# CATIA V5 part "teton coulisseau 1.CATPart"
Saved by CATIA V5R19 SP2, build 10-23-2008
Part number: teton coulisseau 1
Bounding box of the stored display mesh (mm): x -65 to -55, y -11 to -9, z -1 to 1
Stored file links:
  C:\Users\Thinkmotion2\Desktop\Pack 1\IAO_2010_1396_fvigouroux\vigouroux\vigouroux\teton coulisseau 1.CATPart
  C:\Users\Thinkmotion2\Desktop\Pack 1\IAO_2010_1396_fvigouroux\vigouroux\vigouroux\mecanisme IAO.CATProduct
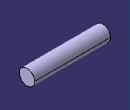
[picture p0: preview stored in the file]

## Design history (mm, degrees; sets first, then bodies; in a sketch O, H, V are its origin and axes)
Set1
  Plane1 to Plane3: linked copy from another document
  Point1: linked copy from another document
Body1 (main body)
  Sketch1 on Plane1, origin (-55, 0, 0), H (0, 1, 0), V (0, 0, 1)
    circle A1 centre (-10, 0) radius 1
    point P1 (-10, 0)
    point P2 (-9, 0)
    reference projected point E1 (-10, 0) from Point1
    radius A1 = 1
    distance P1 E1 = 0
    coincidence: P1 H, A1 P2, P2 H
  Pad1: profile Sketch1, direction (-1, 0, 0), length 10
